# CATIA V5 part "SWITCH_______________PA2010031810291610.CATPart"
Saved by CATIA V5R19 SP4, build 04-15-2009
Part number: SWITCH_______________PA2010031810291610
Bounding box of the stored display mesh (mm): x -7 to 7, y -16.7 to 16.7, z -25.3 to 6.967
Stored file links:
  E:\CadInnWork\1\SWITCH_______________PA2010031810291610.CATPart
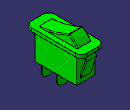
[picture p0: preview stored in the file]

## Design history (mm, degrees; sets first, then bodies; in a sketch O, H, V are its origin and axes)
Parameters
  Update = false
  PDM_version = "A"
  PDM_iteration = 1
  PDM_owner = "moren                    "
  PDM_comment = ""
  PDM_partnumber = "PA002170EA6A57201003181029160010"
Body1 (main body)
  Sketch1 on xy-plane, origin (0, 0, 0), H (1, 0, 0), V (0, 1, 0)
    line L1 (7, 13.2) -> (7, -13.2)
    line L2 (3.5, -16.7) -> (-3.5, -16.7)
    line L3 (-7, -13.2) -> (-7, 13.2)
    line L4 (-3.5, 16.7) -> (3.5, 16.7)
    point P1 (7, 16.7)
    point P2 (7, -16.7)
    point P3 (-7, 16.7)
    arc A1 centre (3.5, 13.2) radius 3.5 from (7, 13.2) to (3.5, 16.7) ccw
    arc A2 centre (-3.5, 13.2) radius 3.5 from (-3.5, 16.7) to (-7, 13.2) ccw
    arc A3 centre (3.5, -13.2) radius 3.5 from (7, -13.2) to (3.5, -16.7) cw
    arc A4 centre (-3.5, -13.2) radius 3.5 from (-3.5, -16.7) to (-7, -13.2) cw
    distance P1 P2 = 33.4
    distance P3 P1 = 14
    radius A1 = 3.5
    radius A2 = 3.5
    radius A3 = 3.5
    radius A4 = 3.5
    vertical: L1 V, L3 V
    horizontal: L2 H, L4 H
    equidistance: L1 L3 O, L2 L4 O
    coincidence: L1 P1, L4 P1, L4 P3, L3 P3, L1 P2, L2 P2
    tangency: A1 L1, A1 L4, A2 L4, A2 L3, A3 L1, A3 L2, A4 L2, A4 L3
  Pad1: profile Sketch1, direction (0, 0, 1), length 2
  Sketch2 on start face of Pad1, origin (0, 0, 0), H (1, 0, 0), V (0, -1, 0)
    line L1 (5.5, 12.5) -> (5.5, -12.5)
    line L2 (5.5, -12.5) -> (-5.5, -12.5)
    line L3 (-5.5, -12.5) -> (-5.5, 12.5)
    line L4 (-5.5, 12.5) -> (5.5, 12.5)
    length L4 = 11
    length L1 = 25
    vertical: L1 V, L3 V
    horizontal: L2 H, L4 H
    equidistance: L1 L3 O, L2 L4 O
  Pad2: profile Sketch2, direction (0, 0, -1), length 16
  Sketch3 on yz-plane, origin (0, 0, 0), H (0, 1, 0), V (0, 0, 1)
    line L1 (14.9583, 0) -> (16.0274, -3.0527)
    point P1 (14.9583, 0)
    line L2 (16.0274, -3.0527) -> (12.5, -13.4489)
    point P3 (12.5, -13.4489)
    reference projected line E1 (12.5, 0) -> (12.5, -16) from edge [face of Pad2 from Sketch2.L1 | face of Pad2 from Sketch2.L2]
    line L3 (14.1636, 0) -> (15.2341, -3.0566)
    point P4 (14.1636, 0)
    line L4 (15.2341, -3.0566) -> (12.5, -11.1147)
    point P6 (12.5, -11.1147)
    reference projected line E2 (12.5, 0) -> (12.5, -16) from edge [face of Pad2 from Sketch2.L1 | face of Pad2 from Sketch2.L2]
    line L5 (14.1636, 0) -> (14.9583, 0)
    line L6 (12.5, -11.1147) -> (12.5, -13.4489)
    distance L3 L1 = 0.75
    distance L4 L2 = 0.75
    coincidence: P1 H, P3 E1, P4 H, P6 E2
    horizontal: L5 H
    vertical: L6 V
  Pad3: profile Sketch3, direction (1, 0, 0), length 3, mirrored extent
  Mirror1: of Pad3, about zx-plane
  Sketch4 on end face of Pad2, origin (0, 0, -16), H (1, 0, 0), V (0, -1, 0)
    line L1 (-2.4148, 10.353) -> (2.4148, 11.647)
    line L2 (2.4148, 11.647) -> (2.4925, 11.3573)
    line L3 (2.4925, 11.3573) -> (-2.3372, 10.0632)
    line L4 (-2.3372, 10.0632) -> (-2.4148, 10.353)
    reference intersected line E1 through (0, 0) direction (1, 0) from zx-plane
    point P5 (0, 11)
    reference intersected line E2 through (0, 0) direction (0, 1) from yz-plane
    distance L1 L3 = 0.3
    length L1 = 5
    angle E1 L3 = 15
    distance H P5 = 11
    perpendicularity: L2 L1
    parallelism: L4 L2
    midpoint: P5 L1
    coincidence: P5 E2
  Pad4: profile Sketch4, direction (0, 0, -1), length 9.3
  Fillet1: radius 2, on edge [face of Pad4 from Sketch4.L4 | end face of Pad4]; edge [face of Pad4 from Sketch4.L2 | end face of Pad4]
  Sketch5 on face of Pad4 from Sketch4.L1, origin (0.1178, -11.0316, -21.9665), H (0.9659, -0.2588, 0), V (0, 0, 1)
    point P1 (-0.1219, 0.6665)
    reference projected line E1 (2.3781, 5.9665) -> (2.3781, -3.3335) from edge [face of Pad4 from Sketch4.L1 | face of Pad4 from Sketch4.L2]
    reference projected line E2 (-2.6219, 5.9665) -> (-2.6219, -3.3335) from edge [face of Pad4 from Sketch4.L4 | face of Pad4 from Sketch4.L1]
    reference projected line E3 (3.3781, -3.3335) -> (-3.6219, -3.3335) from edge [face of Pad4 from Sketch4.L1 | end face of Pad4]
    distance E3 P1 = 4
    equidistance: E1 E2 P1
  Hole1: placed by Sketch5, at (0, -11, -21.3) direction (0.2588, 0.9659, 0), diameter 1, depth 10
  RectPattern1: of Pad4, Fillet1, Hole1, direction 1 instances 2, spacing 9.2, along edge [face of Pad2 from Sketch2.L3 | end face of Pad2]
  Sketch6 on yz-plane, origin (0, 0, 0), H (0, 1, 0), V (0, 0, 1)
    arc A1 centre (-15.7546, 51.8353) radius 50 from (-11.7, 2) to (6.4447, 7.0336) ccw
    point P2 (-11.7, 2)
    point P3 (6.4447, 7.0336)
    arc A2 centre (-0.6288, -5.6115) radius 14.4891 from (6.4447, 7.0336) to (11.7, 2) cw
    point P5 (6.4447, 7.0336)
    point P6 (11.7, 2)
    reference intersected line E1 (-16.7, 2) -> (16.7, 2) from end face of Pad1
    reference intersected line E2 (-16.7, 2) -> (16.7, 2) from end face of Pad1
    reference projected point E3 (-16.7, 2) from edge [face of Pad1 from Sketch1.L2 | end face of Pad1]
    reference projected point E4 (16.7, 2) from edge [face of Pad1 from Sketch1.L4 | end face of Pad1]
    line L1 (11.7, 2) -> (-11.7, 2)
    distance P2 E3 = 5
    distance P6 E4 = 5
    radius A1 = 50
    coincidence: P5 A1, P6 E1, P2 E2, P3 P5
    horizontal: L1 H
  Pad5: profile Sketch6, direction (1, 0, 0), length 4.25, mirrored extent
  Fillet2: radius 0.5, on edge [face of Pad5 from Sketch6.A1 | face of Pad5 from Sketch6.A2]; edge [face of Pad5 from Sketch6.A1 | end face of Pad5]; edge [face of Pad5 from Sketch6.A2 | end face of Pad5]; edge [start face of Pad5 | face of Pad5 from Sketch6.A2]; edge [start face of Pad5 | face of Pad5 from Sketch6.A1]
